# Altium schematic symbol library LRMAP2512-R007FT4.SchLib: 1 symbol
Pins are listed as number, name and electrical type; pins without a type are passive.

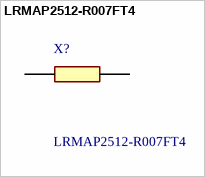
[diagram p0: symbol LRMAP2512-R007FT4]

## LRMAP2512-R007FT4
designator X?
CURRENT SENSE RES, 0R007, 3W, 2512; Resistance:0.007ohm; Product Range:LRMA P Series; Resistor Case Style:2512 [6432 Metric]; Power Rating:3W; Resistance Tolerance:+/- 1%; Resistor Element Type:Metal Alloy RoHS Compliant: Yes; Manufacturer_Name: TT Electronics; Geometry.Height: 0.9mm
footprint RESC6432X90N
pins: 1, 2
